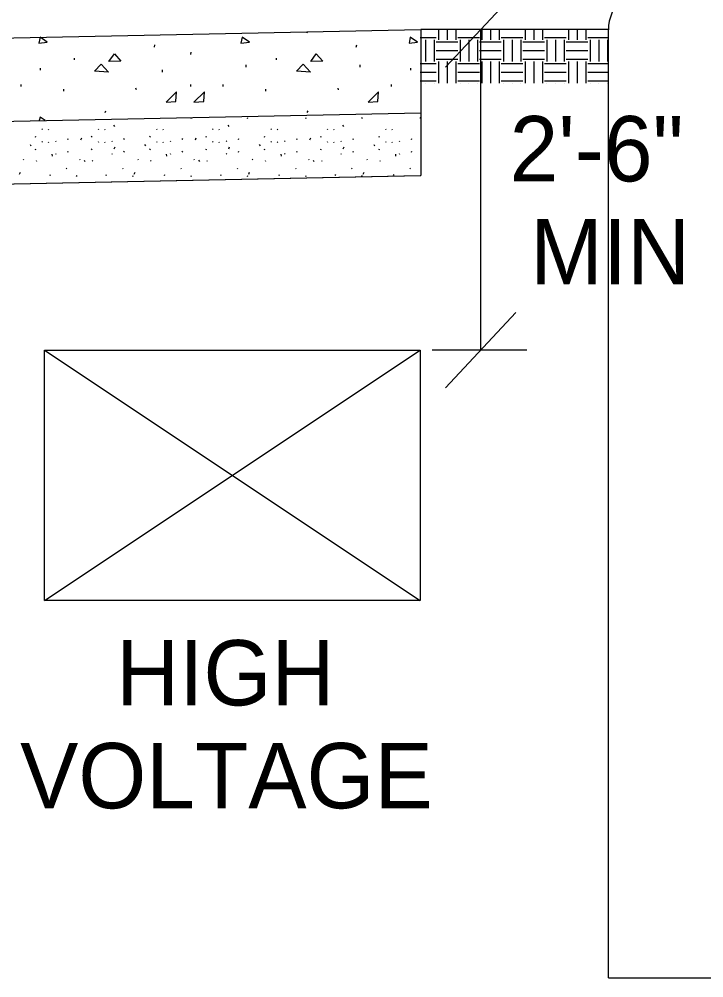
# Model space of a CAD drawing. Extents: x 27101070.6 to 27101150.6, y 1158854.7 to 1158902.9.
# Drawn here: x 27101130.47 to 27101135.94, y 1158881.2 to 1158888.86 of the extents above; entities that cross this region are included whole.
import ezdxf

# ---------------------------------------------------------------- set-up
doc = ezdxf.new("R2010")
doc.units = 0
for name, color, linetype in [('G-ANNO-TEXT', 7, 'Continuous'), ('G-DETL-LINE', 7, 'Continuous'), ('G-DETL-OTLN', 7, 'Continuous'), ('G-DETL-PATT', 7, 'Continuous')]:
    doc.layers.add(name, color=color, linetype=linetype)

msp = doc.modelspace()

# ---------------------------------------------------------------- linework, layer by layer
at = {"layer": 'G-ANNO-TEXT'}
for p, q in [((27101133.8708, 1158888.4778), (27101134.4345, 1158889.079)), ((27101134.1526, 1158888.7784), (27101134.1526, 1158886.2172)), ((27101133.8708, 1158885.9166), (27101134.4345, 1158886.5178)), ((27101134.522, 1158886.2172), (27101133.7642, 1158886.2172))]:
    msp.add_line(p, q, dxfattribs=at)
at = {"layer": 'G-DETL-LINE'}
for p, q in [((27101125.6757, 1158888.6184), (27101133.6741, 1158888.7784)), ((27101133.6741, 1158888.7784), (27101133.6741, 1158887.6126)), ((27101135.1736, 1158888.7784), (27101133.6741, 1158888.7784)), ((27101125.7257, 1158887.9536), (27101133.6741, 1158888.1126)), ((27101127.6954, 1158887.493), (27101133.6693, 1158887.6125)), ((27101129.078, 1158887.5207), (27101133.6741, 1158887.6126))]:
    msp.add_line(p, q, dxfattribs=at)
at = {"layer": 'G-DETL-OTLN'}
for p, q in [((27101135.1736, 1158887.1798), (27101135.1736, 1158888.7777)), ((27101135.1736, 1158881.2026), (27101135.1736, 1158887.1798)), ((27101130.6693, 1158886.2172), (27101133.6693, 1158886.2172)), ((27101130.6693, 1158884.2172), (27101130.6693, 1158886.2172)), ((27101133.6693, 1158886.2172), (27101133.6693, 1158884.2172)), ((27101133.6693, 1158884.2172), (27101130.6693, 1158884.2172)), ((27101135.1736, 1158881.2026), (27101137.1736, 1158881.2026))]:
    msp.add_line(p, q, dxfattribs=at)
msp.add_arc((27101135.5146, 1158888.7777), 0.3409, 90, 180, dxfattribs=at)
at = {"layer": 'G-DETL-PATT'}
for p, q in [((27101133.8158, 1158888.7784), (27101133.8158, 1158888.6969)), ((27101133.885, 1158888.7784), (27101133.885, 1158888.6969)), ((27101133.9543, 1158888.7784), (27101133.9543, 1158888.6969)), ((27101134.1619, 1158888.7784), (27101134.1619, 1158888.6969)), ((27101134.2312, 1158888.7784), (27101134.2312, 1158888.6969)), ((27101134.3004, 1158888.7784), (27101134.3004, 1158888.6969)), ((27101134.5081, 1158888.7784), (27101134.5081, 1158888.6969)), ((27101134.5773, 1158888.7784), (27101134.5773, 1158888.6969)), ((27101134.6465, 1158888.7784), (27101134.6465, 1158888.6969)), ((27101134.8542, 1158888.7784), (27101134.8542, 1158888.6969)), ((27101134.9234, 1158888.7784), (27101134.9234, 1158888.6969)), ((27101134.9926, 1158888.7784), (27101134.9926, 1158888.6969)), ((27101130.6327, 1158888.7176), (27101130.6227, 1158888.6706)), ((27101132.7667, 1158888.7536), (27101132.7702, 1158888.7603)), ((27101133.6701, 1158888.7143), (27101133.7985, 1158888.7143)), ((27101133.7133, 1158888.6969), (27101133.7133, 1158888.5239)), ((27101133.7825, 1158888.6969), (27101133.7825, 1158888.5239)), ((27101133.9716, 1158888.7143), (27101134.1446, 1158888.7143)), ((27101133.9902, 1158888.6969), (27101133.9902, 1158888.5239)), ((27101134.0594, 1158888.6969), (27101134.0594, 1158888.5239)), ((27101134.1286, 1158888.6969), (27101134.1286, 1158888.5239)), ((27101134.3177, 1158888.7143), (27101134.4907, 1158888.7143)), ((27101134.3363, 1158888.6969), (27101134.3363, 1158888.5239)), ((27101134.4055, 1158888.6969), (27101134.4055, 1158888.5239)), ((27101134.4747, 1158888.6969), (27101134.4747, 1158888.5239)), ((27101134.6638, 1158888.7143), (27101134.8369, 1158888.7143)), ((27101134.6824, 1158888.6969), (27101134.6824, 1158888.5239)), ((27101134.7516, 1158888.6969), (27101134.7516, 1158888.5239)), ((27101134.8208, 1158888.6969), (27101134.8208, 1158888.5239)), ((27101135.0099, 1158888.7143), (27101135.1736, 1158888.7143)), ((27101135.0285, 1158888.6969), (27101135.0285, 1158888.5239)), ((27101135.0977, 1158888.6969), (27101135.0977, 1158888.5239)), ((27101135.167, 1158888.6969), (27101135.167, 1158888.5239)), ((27101131.5466, 1158888.6392), (27101131.5486, 1158888.6569)), ((27101133.1595, 1158888.6392), (27101133.1631, 1158888.6569)), ((27101133.7985, 1158888.6809), (27101133.9716, 1158888.6809)), ((27101133.7985, 1158888.6116), (27101133.9716, 1158888.6116)), ((27101134.1446, 1158888.6809), (27101134.3177, 1158888.6809)), ((27101134.1446, 1158888.6116), (27101134.3177, 1158888.6116)), ((27101134.4907, 1158888.6809), (27101134.6638, 1158888.6809)), ((27101134.4907, 1158888.6116), (27101134.6638, 1158888.6116)), ((27101134.8369, 1158888.6809), (27101135.0099, 1158888.6809)), ((27101134.8369, 1158888.6116), (27101135.0099, 1158888.6116)), ((27101130.9082, 1158888.5365), (27101130.9082, 1158888.5501)), ((27101131.8362, 1158888.58), (27101131.8402, 1158888.5972)), ((27101132.5211, 1158888.5365), (27101132.5227, 1158888.5501)), ((27101133.7985, 1158888.5424), (27101133.9716, 1158888.5424)), ((27101134.1446, 1158888.5424), (27101134.3177, 1158888.5424)), ((27101134.4907, 1158888.5424), (27101134.6638, 1158888.5424)), ((27101134.8369, 1158888.5424), (27101135.0099, 1158888.5424)), ((27101130.6374, 1158888.4534), (27101130.6374, 1158888.4701)), ((27101131.6104, 1158888.4387), (27101131.6104, 1158888.4565)), ((27101132.2802, 1158888.4787), (27101132.2802, 1158888.496)), ((27101133.1909, 1158888.4787), (27101133.1909, 1158888.496)), ((27101133.5954, 1158888.4534), (27101133.5954, 1158888.4701)), ((27101133.6701, 1158888.5078), (27101133.7985, 1158888.5078)), ((27101133.8158, 1158888.5251), (27101133.8158, 1158888.352)), ((27101133.885, 1158888.5251), (27101133.885, 1158888.352)), ((27101133.9543, 1158888.5251), (27101133.9543, 1158888.352)), ((27101133.9716, 1158888.5078), (27101134.1446, 1158888.5078)), ((27101134.1619, 1158888.5251), (27101134.1619, 1158888.352)), ((27101134.2312, 1158888.5251), (27101134.2312, 1158888.352)), ((27101134.3004, 1158888.5251), (27101134.3004, 1158888.352)), ((27101134.3177, 1158888.5078), (27101134.4907, 1158888.5078)), ((27101134.5081, 1158888.5251), (27101134.5081, 1158888.352)), ((27101134.5773, 1158888.5251), (27101134.5773, 1158888.352)), ((27101134.6465, 1158888.5251), (27101134.6465, 1158888.352)), ((27101134.6638, 1158888.5078), (27101134.8369, 1158888.5078)), ((27101134.8542, 1158888.5251), (27101134.8542, 1158888.352)), ((27101134.9234, 1158888.5251), (27101134.9234, 1158888.352)), ((27101134.9926, 1158888.5251), (27101134.9926, 1158888.352)), ((27101135.0099, 1158888.5078), (27101135.1736, 1158888.5078)), ((27101133.6701, 1158888.4386), (27101133.7985, 1158888.4386)), ((27101133.9716, 1158888.4386), (27101134.1446, 1158888.4386)), ((27101134.3177, 1158888.4386), (27101134.4907, 1158888.4386)), ((27101134.6638, 1158888.4386), (27101134.8369, 1158888.4386)), ((27101135.0099, 1158888.4386), (27101135.1736, 1158888.4386)), ((27101130.4825, 1158888.3238), (27101130.4825, 1158888.339)), ((27101130.8237, 1158888.2859), (27101130.8237, 1158888.303)), ((27101131.4043, 1158888.298), (27101131.3988, 1158888.3101)), ((27101131.8362, 1158888.3238), (27101131.8362, 1158888.339)), ((27101132.0959, 1158888.3238), (27101132.0959, 1158888.339)), ((27101132.4376, 1158888.2859), (27101132.4376, 1158888.303)), ((27101133.0183, 1158888.298), (27101133.0132, 1158888.3101)), ((27101133.4405, 1158888.3238), (27101133.4405, 1158888.339)), ((27101133.6701, 1158888.3694), (27101133.7985, 1158888.3694)), ((27101133.7133, 1158888.352), (27101133.7133, 1158888.351)), ((27101133.7825, 1158888.352), (27101133.7825, 1158888.351)), ((27101133.9716, 1158888.3694), (27101134.1446, 1158888.3694)), ((27101133.9902, 1158888.352), (27101133.9902, 1158888.351)), ((27101134.0594, 1158888.352), (27101134.0594, 1158888.351)), ((27101134.1286, 1158888.352), (27101134.1286, 1158888.351)), ((27101134.3177, 1158888.3694), (27101134.4907, 1158888.3694)), ((27101134.3363, 1158888.352), (27101134.3363, 1158888.351)), ((27101134.4055, 1158888.352), (27101134.4055, 1158888.351)), ((27101134.4747, 1158888.352), (27101134.4747, 1158888.351)), ((27101134.6638, 1158888.3694), (27101134.8369, 1158888.3694)), ((27101134.6824, 1158888.352), (27101134.6824, 1158888.351)), ((27101134.7516, 1158888.352), (27101134.7516, 1158888.351)), ((27101134.8208, 1158888.352), (27101134.8208, 1158888.351)), ((27101135.0099, 1158888.3694), (27101135.1736, 1158888.3694)), ((27101135.0285, 1158888.352), (27101135.0285, 1158888.351)), ((27101135.0977, 1158888.352), (27101135.0977, 1158888.351)), ((27101135.167, 1158888.352), (27101135.167, 1158888.351)), ((27101131.1537, 1158888.1157), (27101131.1593, 1158888.1294)), ((27101131.8405, 1158888.0686), (27101131.8437, 1158888.076)), ((27101132.2894, 1158888.0686), (27101132.2929, 1158888.0765)), ((27101132.7555, 1158888.0686), (27101132.759, 1158888.0765)), ((27101132.7667, 1158888.1157), (27101132.7738, 1158888.1294)), ((27101133.2045, 1158888.0686), (27101133.208, 1158888.0765)), ((27101133.6706, 1158888.0686), (27101133.6741, 1158888.0765)), ((27101131.2194, 1158888.0161), (27101131.2264, 1158888.0055)), ((27101131.2194, 1158888.0161), (27101131.2264, 1158888.0055)), ((27101131.2194, 1158888.0161), (27101131.2264, 1158888.0055)), ((27101132.1344, 1158888.0161), (27101132.1415, 1158888.0055)), ((27101132.1344, 1158888.0161), (27101132.1415, 1158888.0055)), ((27101132.1344, 1158888.0161), (27101132.1415, 1158888.0055)), ((27101133.0495, 1158888.0161), (27101133.0565, 1158888.0055)), ((27101133.0495, 1158888.0161), (27101133.0565, 1158888.0055)), ((27101133.0495, 1158888.0161), (27101133.0565, 1158888.0055)), ((27101130.596, 1158887.92), (27101130.5995, 1158887.9278)), ((27101130.6477, 1158887.9849), (27101130.6512, 1158887.9796)), ((27101130.6976, 1158887.9829), (27101130.7011, 1158887.9777)), ((27101131.0449, 1158887.92), (27101131.0484, 1158887.9278)), ((27101131.0966, 1158887.9849), (27101131.1001, 1158887.9796)), ((27101131.1465, 1158887.9829), (27101131.15, 1158887.9777)), ((27101131.511, 1158887.92), (27101131.5145, 1158887.9278)), ((27101131.5628, 1158887.9849), (27101131.5663, 1158887.9796)), ((27101131.6127, 1158887.9829), (27101131.6162, 1158887.9777)), ((27101131.96, 1158887.92), (27101131.9635, 1158887.9278)), ((27101132.0117, 1158887.9849), (27101132.0152, 1158887.9796)), ((27101132.0616, 1158887.9829), (27101132.0651, 1158887.9777)), ((27101132.4261, 1158887.92), (27101132.4296, 1158887.9278)), ((27101132.4778, 1158887.9849), (27101132.4813, 1158887.9796)), ((27101132.5277, 1158887.9829), (27101132.5312, 1158887.9777)), ((27101132.875, 1158887.92), (27101132.8785, 1158887.9278)), ((27101132.9268, 1158887.9849), (27101132.9303, 1158887.9796)), ((27101132.9767, 1158887.9829), (27101132.9802, 1158887.9777)), ((27101133.3412, 1158887.92), (27101133.3447, 1158887.9278)), ((27101133.3929, 1158887.9849), (27101133.3964, 1158887.9796)), ((27101133.4428, 1158887.9829), (27101133.4463, 1158887.9777)), ((27101130.5532, 1158887.8605), (27101130.5602, 1158887.85)), ((27101130.5532, 1158887.8605), (27101130.5602, 1158887.85)), ((27101130.5532, 1158887.8605), (27101130.5602, 1158887.85)), ((27101130.6477, 1158887.8843), (27101130.6512, 1158887.879)), ((27101130.6976, 1158887.8823), (27101130.7011, 1158887.8771)), ((27101130.7564, 1158887.8896), (27101130.7599, 1158887.8843)), ((27101130.8544, 1158887.8998), (27101130.858, 1158887.9077)), ((27101130.9587, 1158887.8984), (27101130.9657, 1158887.9142)), ((27101130.9587, 1158887.8984), (27101130.9657, 1158887.9142)), ((27101130.9587, 1158887.8984), (27101130.9657, 1158887.9142)), ((27101131.0966, 1158887.8843), (27101131.1001, 1158887.879)), ((27101131.1465, 1158887.8823), (27101131.15, 1158887.8771)), ((27101131.2053, 1158887.8896), (27101131.2088, 1158887.8843)), ((27101131.3034, 1158887.8998), (27101131.3069, 1158887.9077)), ((27101131.4682, 1158887.8605), (27101131.4753, 1158887.85)), ((27101131.4682, 1158887.8605), (27101131.4753, 1158887.85)), ((27101131.4682, 1158887.8605), (27101131.4753, 1158887.85)), ((27101131.5628, 1158887.8843), (27101131.5663, 1158887.879)), ((27101131.6127, 1158887.8823), (27101131.6162, 1158887.8771)), ((27101131.6714, 1158887.8896), (27101131.6749, 1158887.8843)), ((27101131.7695, 1158887.8998), (27101131.773, 1158887.9077)), ((27101131.8738, 1158887.8984), (27101131.8808, 1158887.9142)), ((27101131.8738, 1158887.8984), (27101131.8808, 1158887.9142)), ((27101131.8738, 1158887.8984), (27101131.8808, 1158887.9142)), ((27101132.0117, 1158887.8843), (27101132.0152, 1158887.879)), ((27101132.0616, 1158887.8823), (27101132.0651, 1158887.8771)), ((27101132.1204, 1158887.8896), (27101132.1239, 1158887.8843)), ((27101132.2185, 1158887.8998), (27101132.222, 1158887.9077)), ((27101132.3833, 1158887.8605), (27101132.3904, 1158887.85)), ((27101132.3833, 1158887.8605), (27101132.3904, 1158887.85)), ((27101132.3833, 1158887.8605), (27101132.3904, 1158887.85)), ((27101132.4778, 1158887.8843), (27101132.4813, 1158887.879)), ((27101132.5277, 1158887.8823), (27101132.5312, 1158887.8771)), ((27101132.5865, 1158887.8896), (27101132.59, 1158887.8843)), ((27101132.6846, 1158887.8998), (27101132.6881, 1158887.9077)), ((27101132.7889, 1158887.8984), (27101132.7959, 1158887.9142)), ((27101132.7889, 1158887.8984), (27101132.7959, 1158887.9142)), ((27101132.7889, 1158887.8984), (27101132.7959, 1158887.9142)), ((27101132.9268, 1158887.8843), (27101132.9303, 1158887.879)), ((27101132.9767, 1158887.8823), (27101132.9802, 1158887.8771)), ((27101133.0354, 1158887.8896), (27101133.039, 1158887.8843)), ((27101133.1335, 1158887.8998), (27101133.137, 1158887.9077)), ((27101133.2983, 1158887.8605), (27101133.3054, 1158887.85)), ((27101133.2983, 1158887.8605), (27101133.3054, 1158887.85)), ((27101133.2983, 1158887.8605), (27101133.3054, 1158887.85)), ((27101133.3929, 1158887.8843), (27101133.3964, 1158887.879)), ((27101133.4428, 1158887.8823), (27101133.4463, 1158887.8771)), ((27101133.5015, 1158887.8896), (27101133.505, 1158887.8843)), ((27101133.5996, 1158887.8998), (27101133.6031, 1158887.9077)), ((27101130.596, 1158887.8193), (27101130.5995, 1158887.8272)), ((27101130.7267, 1158887.7825), (27101130.7285, 1158887.7667)), ((27101130.7267, 1158887.7825), (27101130.7285, 1158887.7667)), ((27101130.7267, 1158887.7825), (27101130.7285, 1158887.7667)), ((27101130.7564, 1158887.789), (27101130.7599, 1158887.7837)), ((27101130.8544, 1158887.7992), (27101130.858, 1158887.8071)), ((27101131.0449, 1158887.8193), (27101131.0484, 1158887.8272)), ((27101131.2053, 1158887.789), (27101131.2088, 1158887.7837)), ((27101131.2251, 1158887.8265), (27101131.2321, 1158887.8423)), ((27101131.2251, 1158887.8265), (27101131.2321, 1158887.8423)), ((27101131.2251, 1158887.8265), (27101131.2321, 1158887.8423)), ((27101131.3034, 1158887.7992), (27101131.3069, 1158887.8071)), ((27101131.511, 1158887.8193), (27101131.5145, 1158887.8272)), ((27101131.6417, 1158887.7825), (27101131.6435, 1158887.7667)), ((27101131.6417, 1158887.7825), (27101131.6435, 1158887.7667)), ((27101131.6417, 1158887.7825), (27101131.6435, 1158887.7667)), ((27101131.6714, 1158887.789), (27101131.6749, 1158887.7837)), ((27101131.7695, 1158887.7992), (27101131.773, 1158887.8071)), ((27101131.96, 1158887.8193), (27101131.9635, 1158887.8272)), ((27101132.1204, 1158887.789), (27101132.1239, 1158887.7837)), ((27101132.1402, 1158887.8265), (27101132.1472, 1158887.8423)), ((27101132.1402, 1158887.8265), (27101132.1472, 1158887.8423)), ((27101132.1402, 1158887.8265), (27101132.1472, 1158887.8423)), ((27101132.2185, 1158887.7992), (27101132.222, 1158887.8071)), ((27101132.4261, 1158887.8193), (27101132.4296, 1158887.8272)), ((27101132.5568, 1158887.7825), (27101132.5586, 1158887.7667)), ((27101132.5568, 1158887.7825), (27101132.5586, 1158887.7667)), ((27101132.5568, 1158887.7825), (27101132.5586, 1158887.7667)), ((27101132.5865, 1158887.789), (27101132.59, 1158887.7837)), ((27101132.6846, 1158887.7992), (27101132.6881, 1158887.8071)), ((27101132.875, 1158887.8193), (27101132.8785, 1158887.8272)), ((27101133.0354, 1158887.789), (27101133.039, 1158887.7837)), ((27101133.0552, 1158887.8265), (27101133.0622, 1158887.8423)), ((27101133.0552, 1158887.8265), (27101133.0622, 1158887.8423)), ((27101133.0552, 1158887.8265), (27101133.0622, 1158887.8423)), ((27101133.1335, 1158887.7992), (27101133.137, 1158887.8071)), ((27101133.3412, 1158887.8193), (27101133.3447, 1158887.8272)), ((27101133.4719, 1158887.7825), (27101133.4737, 1158887.7667)), ((27101133.4719, 1158887.7825), (27101133.4737, 1158887.7667)), ((27101133.4719, 1158887.7825), (27101133.4737, 1158887.7667)), ((27101133.5015, 1158887.789), (27101133.505, 1158887.7837)), ((27101133.5996, 1158887.7992), (27101133.6031, 1158887.8071)), ((27101130.4979, 1158887.7431), (27101130.5014, 1158887.7379)), ((27101130.6014, 1158887.7336), (27101130.6049, 1158887.7284)), ((27101130.9468, 1158887.7431), (27101130.9503, 1158887.7379)), ((27101130.9843, 1158887.736), (27101130.9913, 1158887.7255)), ((27101130.9843, 1158887.736), (27101130.9913, 1158887.7255)), ((27101130.9843, 1158887.736), (27101130.9913, 1158887.7255)), ((27101131.0503, 1158887.7336), (27101131.0539, 1158887.7284)), ((27101131.4129, 1158887.7431), (27101131.4164, 1158887.7379)), ((27101131.5165, 1158887.7336), (27101131.52, 1158887.7284)), ((27101131.8619, 1158887.7431), (27101131.8654, 1158887.7379)), ((27101131.8993, 1158887.736), (27101131.9063, 1158887.7255)), ((27101131.8993, 1158887.736), (27101131.9063, 1158887.7255)), ((27101131.8993, 1158887.736), (27101131.9063, 1158887.7255)), ((27101131.9654, 1158887.7336), (27101131.9689, 1158887.7284)), ((27101132.328, 1158887.7431), (27101132.3315, 1158887.7379)), ((27101132.4315, 1158887.7336), (27101132.435, 1158887.7284)), ((27101132.7769, 1158887.7431), (27101132.7804, 1158887.7379)), ((27101132.8144, 1158887.736), (27101132.8214, 1158887.7255)), ((27101132.8144, 1158887.736), (27101132.8214, 1158887.7255)), ((27101132.8144, 1158887.736), (27101132.8214, 1158887.7255)), ((27101132.8805, 1158887.7336), (27101132.884, 1158887.7284)), ((27101133.243, 1158887.7431), (27101133.2465, 1158887.7379)), ((27101133.3466, 1158887.7336), (27101133.3501, 1158887.7284)), ((27101130.4695, 1158887.6232), (27101130.4765, 1158887.639)), ((27101130.4695, 1158887.6232), (27101130.4765, 1158887.639)), ((27101130.4695, 1158887.6232), (27101130.4765, 1158887.639)), ((27101130.7125, 1158887.6126), (27101130.716, 1158887.6205)), ((27101130.8428, 1158887.6714), (27101130.8463, 1158887.6661)), ((27101131.1614, 1158887.6126), (27101131.165, 1158887.6205)), ((27101131.2917, 1158887.6714), (27101131.2953, 1158887.6661)), ((27101131.3846, 1158887.6232), (27101131.3916, 1158887.639)), ((27101131.3846, 1158887.6232), (27101131.3916, 1158887.639)), ((27101131.3846, 1158887.6232), (27101131.3916, 1158887.639)), ((27101131.6276, 1158887.6126), (27101131.631, 1158887.6205)), ((27101131.7579, 1158887.6714), (27101131.7614, 1158887.6661)), ((27101132.0765, 1158887.6126), (27101132.08, 1158887.6205)), ((27101132.2068, 1158887.6714), (27101132.2103, 1158887.6661)), ((27101132.2997, 1158887.6232), (27101132.3066, 1158887.639)), ((27101132.2997, 1158887.6232), (27101132.3066, 1158887.639)), ((27101132.2997, 1158887.6232), (27101132.3066, 1158887.639)), ((27101132.5426, 1158887.6126), (27101132.5461, 1158887.6205)), ((27101132.6729, 1158887.6714), (27101132.6765, 1158887.6661)), ((27101132.9916, 1158887.6126), (27101132.9951, 1158887.6205)), ((27101133.1219, 1158887.6714), (27101133.1254, 1158887.6661)), ((27101133.2147, 1158887.6232), (27101133.2217, 1158887.639)), ((27101133.2147, 1158887.6232), (27101133.2217, 1158887.639)), ((27101133.2147, 1158887.6232), (27101133.2217, 1158887.639)), ((27101133.4577, 1158887.6126), (27101133.4612, 1158887.6205)), ((27101133.588, 1158887.6714), (27101133.5915, 1158887.6661)), ((27101130.9254, 1158887.6047), (27101130.9289, 1158887.6126)), ((27101131.3744, 1158887.6047), (27101131.3779, 1158887.6126)), ((27101131.8405, 1158887.6047), (27101131.844, 1158887.6126)), ((27101132.2894, 1158887.6047), (27101132.2929, 1158887.6126)), ((27101132.7555, 1158887.6047), (27101132.759, 1158887.6126)), ((27101133.2045, 1158887.6047), (27101133.208, 1158887.6126)), ((27101130.6693, 1158884.2172), (27101133.6693, 1158886.2172)), ((27101130.6693, 1158886.2172), (27101133.6693, 1158884.2172))]:
    msp.add_line(p, q, dxfattribs=at)
for points in [[(27101130.6227, 1158888.6706), (27101130.6905, 1158888.6792), (27101130.6337, 1158888.7176)], [(27101130.6739, 1158888.0526), (27101130.6328, 1158888.0803), (27101130.6267, 1158888.0516)]]:
    msp.add_lwpolyline(points, dxfattribs=at)
for points in [[(27101132.2371, 1158888.6706), (27101132.305, 1158888.6792), (27101132.2473, 1158888.7182)], [(27101133.5807, 1158888.6706), (27101133.6486, 1158888.6792), (27101133.5909, 1158888.7182)], [(27101131.1811, 1158888.5243), (27101131.2266, 1158888.5855), (27101131.2783, 1158888.5273)], [(27101132.7955, 1158888.5243), (27101132.8396, 1158888.5855), (27101132.8927, 1158888.5273)], [(27101131.0667, 1158888.4453), (27101131.1214, 1158888.5025), (27101131.1796, 1158888.4382)], [(27101132.6811, 1158888.4453), (27101132.7338, 1158888.5025), (27101132.794, 1158888.4382)], [(27101131.7187, 1158888.2049), (27101131.7223, 1158888.2813), (27101131.6392, 1158888.1998)], [(27101131.9415, 1158888.2049), (27101131.9456, 1158888.2813), (27101131.862, 1158888.1998)], [(27101133.3316, 1158888.2049), (27101133.3367, 1158888.2813), (27101133.2532, 1158888.1998)]]:
    msp.add_lwpolyline(points, close=True, dxfattribs=at)

# ---------------------------------------------------------------- texts
at = {"layer": 'G-ANNO-TEXT'}
for s, p in [('2\'-6"', (27101134.3845, 1158887.5661)), ('MIN', (27101134.5477, 1158886.7441)), ('HIGH', (27101131.24, 1158883.379)), ('VOLTAGE', (27101130.4733, 1158882.557))]:
    msp.add_text(s, height=0.522, dxfattribs=at).set_placement(p)

doc.saveas('drawing.dxf')
